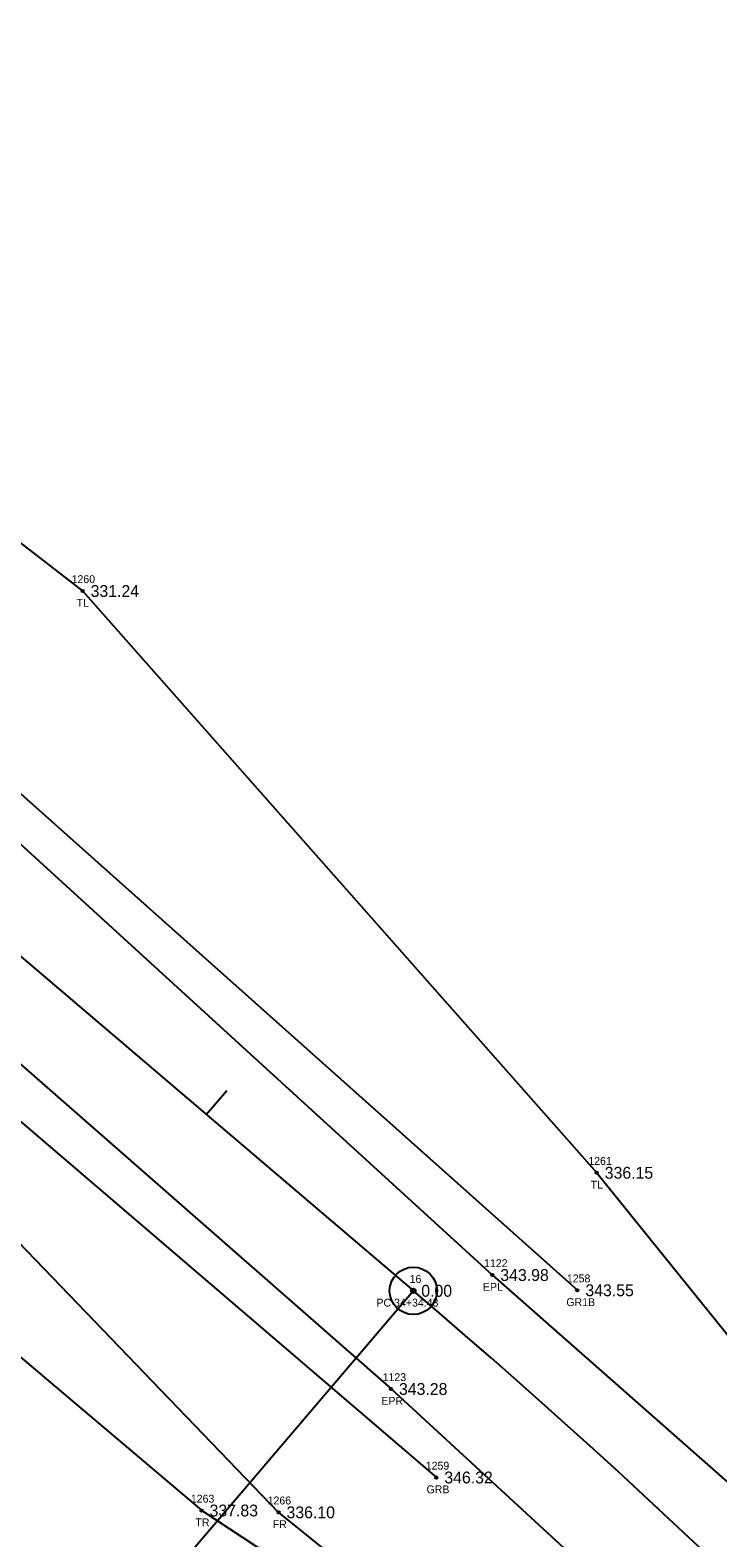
# Model space of a CAD drawing. Extents: x 2006517 to 2008868, y 1001613 to 1004633.
# Drawn here: x 2007945.8 to 2008032.9, y 1002790.5 to 1002981.4 of the extents above; entities that cross this region are included whole.
import ezdxf

# ---------------------------------------------------------------- set-up
doc = ezdxf.new("R2010")
doc.units = 0
for name, color, linetype in [('RD_EX_Fence_Other', 7, 'Continuous'), ('RD_EX_Fence_Other_txCode', 7, 'Continuous'), ('RD_EX_GuardRail', 7, 'Continuous'), ('RD_EX_GuardRail_txCode', 7, 'Continuous'), ('RD_EX_Road', 7, 'Continuous'), ('RD_EX_Road_txCode', 7, 'Continuous'), ('RD_EX_TX_Fence_Other_ELEV', 7, 'Continuous'), ('RD_EX_TX_GuardRail_ELEV', 7, 'Continuous'), ('RD_EX_TX_Road_ELEV', 7, 'Continuous'), ('RD_EX_TX_VEG_ELEV', 7, 'Continuous'), ('RD_EX_VEG', 7, 'Continuous'), ('RD_EX_VEG_txCode', 7, 'Continuous'), ('RD_HC_Cl', 7, 'Continuous'), ('RD_HC_Data', 7, 'Continuous'), ('RD_HC_Data_Tic', 7, 'Continuous'), ('RD_HC_Survey_ELEV', 7, 'Continuous'), ('RD_HC_txCode', 7, 'Continuous'), ('RD_SMD_Locator', 7, 'Continuous')]:
    doc.layers.add(name, color=color, linetype=linetype)

msp = doc.modelspace()

# ---------------------------------------------------------------- linework, layer by layer
at = {"layer": 'RD_EX_Fence_Other'}
msp.add_lwpolyline([(2007893.11, 1002837.65), (2007909.33, 1002864.32), (2007977.3, 1002793.73), (2008015.3, 1002762.96), (2008043.08, 1002729.4), (2008077.68, 1002692.52), (2008105.37, 1002656.99), (2008134.4, 1002618.61), (2008158.01, 1002583.52)], dxfattribs=at)
at = {"layer": 'RD_EX_GuardRail'}
for points in [[(2007643.64, 1003141.95), (2007706.71, 1003087.87), (2007781.32, 1003024.2), (2007854.58, 1002961.97), (2007936.8, 1002891.67), (2008015.14, 1002821.85)], [(2007623.33, 1003114.9), (2007686.46, 1003063.73), (2007759.92, 1003000.81), (2007833.42, 1002938.17), (2007916.12, 1002867.57), (2007997.28, 1002798.14)]]:
    msp.add_lwpolyline(points, dxfattribs=at)
at = {"layer": 'RD_EX_Road'}
for points in [[(2007926.53, 1002880.46), (2007933.33, 1002888.64), (2008004.37, 1002823.78), (2008041.16, 1002791.39), (2008076.97, 1002755.85), (2008109.64, 1002720.02), (2008140.82, 1002682.03), (2008169.79, 1002642.37), (2008196.81, 1002603.48), (2008249.05, 1002522.64), (2008259.94, 1002505.27), (2008271.29, 1002488.2), (2008299.71, 1002443.6), (2008349.96, 1002366.27), (2008401.09, 1002286.99), (2008453.35, 1002207.39), (2008504.32, 1002128.41), (2008557.14, 1002047.24), (2008604.7, 1001974.22), (2008628.71, 1001937.76), (2008659.22, 1001891.69), (2008712.34, 1001810.72), (2008764.8, 1001729.24), (2008801.79, 1001664.14)], [(2007926.53, 1002880.46), (2007919.41, 1002872.5), (2007991.54, 1002809.35), (2008026.83, 1002776.85), (2008062.37, 1002741.51), (2008093.99, 1002707.06), (2008125.02, 1002669.01), (2008154.41, 1002630.27), (2008179.59, 1002592.85), (2008187.94, 1002580.41), (2008232, 1002511.78), (2008283.05, 1002433.59)]]:
    msp.add_lwpolyline(points, dxfattribs=at)
at = {"layer": 'RD_EX_VEG'}
for points in [[(2007395.89, 1003327.12), (2007429.8, 1003285.17), (2007467.04, 1003247.92), (2007498.61, 1003210.85), (2007670.4, 1003045.37), (2007967.56, 1002793.96), (2008054.61, 1002736.66), (2008078.76, 1002693.39), (2008113.28, 1002661.09), (2008135.36, 1002619.06), (2008159.5, 1002583.06), (2008222.5, 1002503.36), (2008272.84, 1002426.91), (2008323.43, 1002347.7), (2008431.42, 1002192), (2008479.95, 1002108.23), (2008533.09, 1002033.28), (2008631.97, 1001873.89), (2008775.08, 1001653.06)], [(2007473.93, 1003322.69), (2007503.07, 1003282.99), (2007540.25, 1003252.05), (2007579.27, 1003219.13), (2007642.18, 1003150.48), (2007952.5, 1002910.4), (2008017.59, 1002836.73), (2008047.98, 1002799.05), (2008087.42, 1002767.09), (2008121.48, 1002729.06), (2008151.49, 1002690.42), (2008185.86, 1002650.76), (2008208.76, 1002609.15), (2008254.04, 1002533.01), (2008311.38, 1002450.28), (2008360.35, 1002372.97), (2008409.06, 1002292.02), (2008460.63, 1002215.28), (2008512.48, 1002133.62), (2008564.88, 1002053.16), (2008614.62, 1001980.71), (2008661.43, 1001938.2)]]:
    msp.add_lwpolyline(points, dxfattribs=at)
at = {"layer": 'RD_HC_Cl'}
msp.add_line((2007559.77, 1003192.01), (2007994.36, 1002821.78), dxfattribs=at)
msp.add_arc((2007371.33, 1002090.43), 960.75, 33.06116, 49.57273, dxfattribs=at)
at = {"layer": 'RD_HC_Data'}
msp.add_line((2007994.36, 1002821.78), (2007918.85, 1002733.14), dxfattribs=at)
for radius in [3, 0.282]:
    msp.add_circle((2007994.36, 1002821.78), radius, dxfattribs=at)
at = {"layer": 'RD_HC_Data_Tic'}
msp.add_line((2007968.15, 1002844.11), (2007970.75, 1002847.16), dxfattribs=at)
at = {"layer": 'RD_SMD_Locator'}
for centre in [(2007952.5, 1002910.4), (2008017.59, 1002836.73), (2008004.37, 1002823.78), (2007994.36, 1002821.78), (2008015.14, 1002821.85), (2007991.54, 1002809.35), (2007997.28, 1002798.14), (2007967.56, 1002793.96), (2007977.3, 1002793.73)]:
    msp.add_circle(centre, 0.15, dxfattribs=at)

# ---------------------------------------------------------------- texts
at = {"layer": 'RD_EX_Fence_Other_txCode'}
for s, p in [('1266', (2007975.91, 1002794.73)), ('FR', (2007976.55, 1002791.73))]:
    msp.add_text(s, height=1, dxfattribs=at).set_placement(p)
at = {"layer": 'RD_EX_GuardRail_txCode'}
for s, p in [('1258', (2008013.8, 1002822.85)), ('GR1B', (2008013.73, 1002819.85)), ('1259', (2007995.93, 1002799.14)), ('GRB', (2007996.03, 1002796.14))]:
    msp.add_text(s, height=1, dxfattribs=at).set_placement(p)
at = {"layer": 'RD_EX_Road_txCode'}
for s, p in [('1122', (2008003.31, 1002824.78)), ('EPL', (2008003.17, 1002821.78)), ('1123', (2007990.47, 1002810.35)), ('EPR', (2007990.31, 1002807.35))]:
    msp.add_text(s, height=1, dxfattribs=at).set_placement(p)
at = {"layer": 'RD_EX_TX_Fence_Other_ELEV'}
msp.add_text('336.10', height=1.5, dxfattribs=at).set_placement((2007978.3, 1002792.98))
at = {"layer": 'RD_EX_TX_GuardRail_ELEV'}
for s, p in [('343.55', (2008016.14, 1002821.1)), ('346.32', (2007998.28, 1002797.39))]:
    msp.add_text(s, height=1.5, dxfattribs=at).set_placement(p)
at = {"layer": 'RD_EX_TX_Road_ELEV'}
for s, p in [('343.98', (2008005.37, 1002823.03)), ('343.28', (2007992.54, 1002808.6))]:
    msp.add_text(s, height=1.5, dxfattribs=at).set_placement(p)
at = {"layer": 'RD_EX_TX_VEG_ELEV'}
for s, p in [('331.24', (2007953.5, 1002909.65)), ('336.15', (2008018.59, 1002835.98)), ('337.83', (2007968.56, 1002793.21))]:
    msp.add_text(s, height=1.5, dxfattribs=at).set_placement(p)
at = {"layer": 'RD_EX_VEG_txCode'}
for s, p in [('1260', (2007951.09, 1002911.4)), ('TL', (2007951.72, 1002908.4)), ('1261', (2008016.51, 1002837.73)), ('TL', (2008016.82, 1002834.73)), ('1263', (2007966.19, 1002794.96)), ('TR', (2007966.77, 1002791.96))]:
    msp.add_text(s, height=1, dxfattribs=at).set_placement(p)
at = {"layer": 'RD_HC_Survey_ELEV'}
msp.add_text('0.00', height=1.5, dxfattribs=at).set_placement((2007995.36, 1002821.03))
at = {"layer": 'RD_HC_txCode'}
for s, p in [('16', (2007993.89, 1002822.78)), ('PC 34+34.43', (2007989.69, 1002819.78))]:
    msp.add_text(s, height=1, dxfattribs=at).set_placement(p)

doc.saveas('drawing.dxf')
